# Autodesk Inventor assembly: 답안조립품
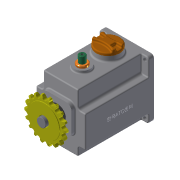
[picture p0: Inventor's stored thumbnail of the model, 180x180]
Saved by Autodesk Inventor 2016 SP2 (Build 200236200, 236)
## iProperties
Created: 2017-12
Part Number: 답안조립품
Document SubType Name: Assembly
Designer: Administrator
Mass: 2736.08 g
Surface Area: 2015.6 cm^2
Volume: 734.133 cm^3
Density: 3.72696 g/cm^3
Author: Administrator
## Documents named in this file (17)
- D:\371207V1008\답안조립품.iam
- D:\371207V1008\본체.ipt
- D:\371207V1008\부시.ipt
- D:\371207V1008\슬라이더.ipt
- D:\371207V1008\스프로킷.ipt
- D:\371207V1008\오일 실 17 32 8.ipt
- D:\371207V1008\베어링 608.ipt
- D:\371207V1008\베어링 6003.ipt
- D:\371207V1008\메인축.ipt
- D:\371207V1008\서브축.ipt
- D:\371207V1008\키 5 x 5 x 18.ipt
- D:\371207V1008\상부 캡.ipt
- D:\371207V1008\멈춤나사 M3x8.ipt
- D:\371207V1008\커버.ipt
- D:\371207V1008\오일 실 8 22 7.ipt
- D:\371207V1008\볼트 M4 x 10.ipt
- D:\371207V1008\가변스프링.ipt
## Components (1 placed, 1 different names)
1. 가변스프링:1
